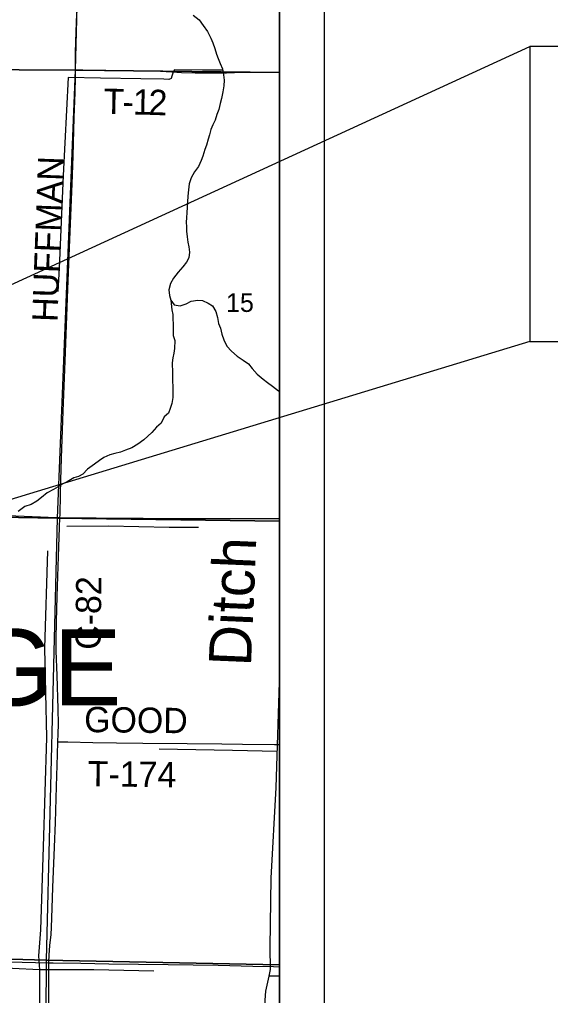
# Model space of a CAD drawing. Extents: x 0 to 39.4, y 0 to 22.
# Drawn here: x 8.317 to 9.507, y 17.227 to 19.416 of the extents above; entities that cross this region are included whole.
import ezdxf

# ---------------------------------------------------------------- set-up
doc = ezdxf.new("R2010")
doc.units = 0
for name, color, linetype in [('Default', 7, 'Continuous'), ('GM_X_County_Road', 7, 'Continuous'), ('GM_X_County_Road_Text', 7, 'Continuous'), ('GM_X_Interstate_Route', 7, 'Continuous'), ('GM_X_Minor_River', 7, 'Continuous'), ('GM_X_Minor_River_Text', 7, 'Continuous'), ('GM_X_Section', 7, 'Continuous'), ('GM_X_Section_Text', 7, 'Continuous'), ('GM_X_State_Route', 7, 'Continuous'), ('GM_X_Township_Road', 7, 'Continuous'), ('GM_X_Township_Road_Text', 7, 'Continuous'), ('GM_X_Township_Text', 7, 'Continuous'), ('SH_Data', 7, 'Continuous')]:
    doc.layers.add(name, color=color, linetype=linetype)

msp = doc.modelspace()

# ---------------------------------------------------------------- linework, layer by layer
at = {"layer": 'Default'}
for points in [[(8.9, 19.2971), (8.9, 20.3024), (8.4681, 20.3039), (8.4416, 19.3027)], [(8.9, 18.2912), (8.9, 19.2971), (8.4416, 19.3027), (8.401, 18.2978)], [(8.9, 17.2957), (8.9, 18.2912), (8.401, 18.2978), (8.3769, 17.3064)], [(8.9, 16.3001), (8.9, 17.2957), (8.3769, 17.3064), (8.3707, 16.3273)]]:
    msp.add_lwpolyline(points, close=True, dxfattribs=at)
at = {"layer": 'GM_X_County_Road'}
for points in [[(8.4422, 19.3032), (8.4421, 19.3175), (8.4427, 19.3423), (8.4442, 19.3889), (8.4455, 19.4293), (8.4473, 19.4759), (8.4489, 19.5287), (8.4524, 19.6343), (8.458, 19.7958), (8.4596, 19.8393), (8.4605, 19.8735), (8.4618, 19.917), (8.4638, 19.9822), (8.467, 20.0909), (8.4725, 20.2649), (8.4739, 20.3065)], [(8.4075, 18.2991), (8.4077, 18.305), (8.409, 18.3515), (8.4097, 18.3826), (8.4113, 18.4323), (8.4151, 18.5379), (8.4193, 18.6497), (8.4255, 18.8112), (8.4297, 18.923), (8.4318, 18.9758), (8.4347, 19.0473), (8.4371, 19.1094), (8.4398, 19.1963), (8.4417, 19.2522), (8.4422, 19.2864), (8.4422, 19.3032)], [(7.9066, 18.3132), (7.9262, 18.3132), (7.9915, 18.3125), (8.0381, 18.3111), (8.0629, 18.3103), (8.1127, 18.3094), (8.209, 18.3066), (8.2618, 18.3048), (8.3084, 18.3031), (8.3643, 18.3008), (8.3985, 18.2993), (8.4075, 18.2991)], [(8.4032, 17.7958), (8.4038, 17.8141), (8.404, 17.8359), (8.4035, 17.87), (8.4011, 17.9446), (8.3994, 18.0005), (8.3992, 18.0254), (8.3998, 18.0658), (8.401, 18.1217), (8.4044, 18.2118), (8.4066, 18.277), (8.4075, 18.2991)], [(8.4075, 18.2991), (8.4327, 18.2986), (8.4886, 18.2983), (8.5508, 18.298), (8.5943, 18.2979), (8.6596, 18.2972), (8.7311, 18.2969), (8.8026, 18.2966), (8.8772, 18.2967), (8.9, 18.2966)], [(8.3824, 17.3006), (8.3824, 17.3019), (8.3832, 17.3174), (8.3852, 17.3391), (8.3877, 17.3638), (8.3887, 17.3793), (8.3905, 17.4228), (8.3918, 17.4694), (8.3951, 17.5595), (8.3973, 17.6153), (8.4, 17.6961), (8.4022, 17.7675), (8.4032, 17.7958)], [(8.3715, 16.3333), (8.3721, 16.3573), (8.3759, 16.5157), (8.377, 16.5654), (8.3794, 16.6586), (8.381, 16.7114), (8.3832, 16.7984), (8.3843, 16.8357), (8.3844, 16.8668), (8.3837, 16.9289), (8.3834, 16.9849), (8.3834, 17.0843), (8.3832, 17.1589), (8.3826, 17.2086), (8.3825, 17.2801), (8.3824, 17.3006)]]:
    msp.add_lwpolyline(points, dxfattribs=at)
at = {"layer": 'GM_X_Interstate_Route'}
msp.add_lwpolyline([(8.9, 15.3132), (8.9, 20.9)], dxfattribs=at)
at = {"layer": 'GM_X_Minor_River'}
msp.add_line((8.9, 17.2705), (8.876, 17.2704), dxfattribs=at)
for points in [[(8.706, 19.4263), (8.7195, 19.4158), (8.7288, 19.4027), (8.7384, 19.3896), (8.7457, 19.3747), (8.7501, 19.364), (8.7552, 19.351), (8.7584, 19.3384), (8.762, 19.3288), (8.7671, 19.3177), (8.7719, 19.3059), (8.7746, 19.2921), (8.7756, 19.28), (8.775, 19.2674), (8.7728, 19.2538), (8.7695, 19.2387), (8.767, 19.2281), (8.7637, 19.2145), (8.7593, 19.2032), (8.7553, 19.1907), (8.7506, 19.1798), (8.7458, 19.1692), (8.7429, 19.1579), (8.7397, 19.1477), (8.7364, 19.1344), (8.7324, 19.1243), (8.7276, 19.1099), (8.7244, 19.0997), (8.7185, 19.0865), (8.7091, 19.0742), (8.7017, 19.061), (8.6976, 19.0474), (8.6958, 19.0338), (8.6944, 19.0197), (8.6935, 19.0072), (8.6932, 18.9947), (8.6923, 18.9833), (8.6913, 18.9712), (8.6907, 18.9617), (8.6917, 18.9511), (8.6915, 18.9416), (8.6928, 18.929), (8.6945, 18.9168), (8.6966, 18.9065), (8.6982, 18.894), (8.6965, 18.8818), (8.691, 18.8721), (8.6832, 18.8616), (8.6727, 18.8496), (8.6622, 18.8361), (8.6552, 18.8237), (8.6515, 18.8101), (8.6532, 18.7968), (8.656, 18.7865), (8.6638, 18.7761), (8.6774, 18.7743), (8.6904, 18.7783), (8.7019, 18.7841), (8.7168, 18.7865), (8.7274, 18.7856), (8.7399, 18.78), (8.7496, 18.7738), (8.7574, 18.7615), (8.761, 18.7478), (8.7634, 18.7344)], [(8.7725, 19.3028), (8.7269, 19.3029), (8.6643, 19.3033), (8.6611, 19.298), (8.6587, 19.2889), (8.6567, 19.284), (8.6517, 19.2819), (8.6403, 19.2824), (8.589, 19.283), (8.4986, 19.2843), (8.4257, 19.2864), (8.4151, 19.0663), (8.4055, 18.8584), (8.4031, 18.806)], [(8.656, 18.7865), (8.6583, 18.7652), (8.6604, 18.7545), (8.6609, 18.7435), (8.6611, 18.734), (8.6617, 18.7207), (8.6614, 18.7074), (8.665, 18.6963), (8.6643, 18.6785), (8.6626, 18.6679), (8.6605, 18.6577), (8.6595, 18.6459), (8.6599, 18.6239), (8.6601, 18.6136), (8.6599, 18.6041), (8.6605, 18.5939), (8.6607, 18.584), (8.6604, 18.5684), (8.6583, 18.5548), (8.655, 18.5434), (8.651, 18.5333), (8.641, 18.5251), (8.6347, 18.5108), (8.6239, 18.5018), (8.6134, 18.4902), (8.5956, 18.4731), (8.5825, 18.4638), (8.5691, 18.4553), (8.5549, 18.4503), (8.543, 18.4459), (8.5304, 18.4427), (8.5197, 18.4395), (8.506, 18.4337), (8.496, 18.427), (8.4848, 18.4189), (8.4694, 18.4074), (8.4589, 18.3965), (8.4489, 18.391), (8.439, 18.3878), (8.4236, 18.379), (8.4137, 18.375), (8.4033, 18.3679), (8.3929, 18.3617), (8.3791, 18.3543), (8.366, 18.3439), (8.356, 18.3361), (8.3429, 18.3287), (8.3292, 18.3237), (8.3138, 18.3129)], [(8.7634, 18.7344), (8.7674, 18.7237), (8.7705, 18.7104), (8.7752, 18.6978), (8.7818, 18.6836), (8.7919, 18.6724), (8.805, 18.6608), (8.8181, 18.6518), (8.8305, 18.644), (8.8383, 18.6336), (8.8495, 18.6205), (8.863, 18.6096), (8.8731, 18.6022), (8.8843, 18.594), (8.8974, 18.5835), (8.9, 18.5811)], [(8.4232, 18.2796), (8.5163, 18.2802), (8.6526, 18.2777), (8.7184, 18.2773)], [(8.3796, 18.2246), (8.3733, 18.0063), (8.3771, 17.8061), (8.3703, 17.5605), (8.3638, 17.3741), (8.3593, 17.316), (8.3618, 17.2848), (8.3616, 17.1762), (8.3606, 16.8731), (8.3565, 16.6533), (8.3505, 16.4353), (8.3496, 16.3256), (8.3537, 16.2978), (8.35, 16.1835), (8.3462, 16.0594), (8.343, 15.9276), (8.3395, 15.8198), (8.3375, 15.715), (8.3335, 15.5829), (8.3325, 15.4465), (8.3289, 15.3345)], [(8.9, 17.9539), (8.892, 17.6933), (8.8804, 17.4903), (8.8779, 17.3357), (8.8786, 17.2856), (8.876, 17.2704), (8.8686, 17.2371), (8.8671, 17.2166), (8.8652, 17.1794), (8.8683, 17.0958), (8.8668, 16.9093), (8.8612, 16.7229), (8.861, 16.6036), (8.8598, 16.4958), (8.8594, 16.4323), (8.8568, 16.3709), (8.856, 16.3469)], [(8.8945, 17.7746), (8.7945, 17.7764), (8.63, 17.7794)], [(8.6181, 17.2813), (8.4837, 17.2849), (8.3618, 17.2848), (8.2399, 17.2905), (8.0075, 17.297), (7.8849, 17.3008)]]:
    msp.add_lwpolyline(points, dxfattribs=at)
at = {"layer": 'GM_X_Section'}
for points in [[(8.4681, 20.3039), (8.4416, 19.3027), (7.439, 19.3083), (7.4647, 20.3092)], [(8.4416, 19.3027), (8.401, 18.2978), (7.4046, 18.3152), (7.439, 19.3083)], [(8.401, 18.2978), (8.3769, 17.3064), (7.3784, 17.3348), (7.4046, 18.3152)], [(8.3769, 17.3064), (8.3707, 16.3273), (7.3732, 16.344), (7.3784, 17.3348)]]:
    msp.add_lwpolyline(points, close=True, dxfattribs=at)
at = {"layer": 'GM_X_State_Route'}
for points in [[(6.8016, 17.3392), (6.898, 17.3386), (6.9881, 17.3378), (7.0534, 17.3371), (7.1342, 17.3365), (7.1933, 17.3358), (7.3704, 17.3333), (7.3804, 17.3331), (7.4046, 17.3325), (7.4605, 17.3304), (7.5195, 17.3285), (7.5755, 17.3267), (7.7712, 17.3196), (7.8582, 17.3167), (7.9265, 17.3146), (7.9762, 17.3125), (8.0632, 17.3097), (8.2123, 17.3053), (8.2931, 17.3024), (8.3824, 17.3006)], [(8.3824, 17.3006), (8.3926, 17.3003), (8.4547, 17.2996), (8.5169, 17.2983), (8.6505, 17.2967), (8.7065, 17.2958), (8.7624, 17.2949), (8.8401, 17.2928), (8.8867, 17.292), (8.9, 17.2917)]]:
    msp.add_lwpolyline(points, dxfattribs=at)
at = {"layer": 'GM_X_Township_Road'}
for points in [[(7.9433, 19.3081), (7.9681, 19.3078), (8.0147, 19.3076), (8.0396, 19.3072), (8.0893, 19.3067), (8.1328, 19.306), (8.1701, 19.3058), (8.2074, 19.3052), (8.2913, 19.304), (8.397, 19.3031), (8.4405, 19.3033), (8.4422, 19.3032)], [(8.4422, 19.3032), (8.4592, 19.303), (8.5618, 19.3017), (8.5991, 19.3014), (8.6332, 19.3003), (8.6581, 19.2989), (8.6798, 19.2976), (8.7109, 19.2967), (8.7357, 19.2967), (8.7575, 19.2965), (8.7754, 19.2966), (8.7812, 19.2968), (8.7864, 19.297), (8.7989, 19.2975), (8.8146, 19.298), (8.8258, 19.298), (8.841, 19.2982), (8.86, 19.2978), (8.9, 19.2972)], [(8.4032, 17.7958), (8.41, 17.7957), (8.4255, 17.7957), (8.4814, 17.7945), (8.5342, 17.7939), (8.5932, 17.7933), (8.6926, 17.7924), (8.7703, 17.7915), (8.8169, 17.7911), (8.8884, 17.7901), (8.9, 17.7899)]]:
    msp.add_lwpolyline(points, dxfattribs=at)
at = {"layer": 'SH_Data'}
for p, q in [((9, 21), (9, 14)), ((8.9, 20.9), (8.9, 14.1))]:
    msp.add_line(p, q, dxfattribs=at)
for points in [[(9.4615, 18.6937), (5.1869, 17.3921), (9.4615, 19.3557)], [(9.4615, 18.6937), (10.9611, 18.6937), (10.9611, 19.3557), (9.4615, 19.3557)]]:
    msp.add_lwpolyline(points, close=True, dxfattribs=at)

# ---------------------------------------------------------------- texts
at = {"layer": 'GM_X_County_Road_Text'}
for s, rotation, p in [('HUFFMAN', 87.8986, (8.4019, 18.7372)), ('C-82', 89.3324, (8.4988, 18.0023))]:
    msp.add_text(s, height=0.05682, rotation=rotation, dxfattribs=at).set_placement(p)
at = {"layer": 'GM_X_Minor_River_Text'}
msp.add_text('Ditch', height=0.09475, rotation=87.577, dxfattribs=at).set_placement((8.8358, 17.9644))
at = {"layer": 'GM_X_Section_Text'}
msp.add_text('15', height=0.04186, rotation=0, dxfattribs=at).set_placement((8.7801, 18.7603))
at = {"layer": 'GM_X_Township_Road_Text'}
for s, height, rotation, p in [('T', 0.0568, 358.8685, (8.5048, 19.2045)), ('1', 0.0568, 358.777, (8.5706, 19.2032)), ('2', 0.0568, 358.3344, (8.6055, 19.2024)), ('-', 0.0568, 358.8525, (8.5473, 19.2037)), ('GOOD', 0.05682, 359.2898, (8.4616, 17.8179)), ('T-174', 0.05682, 359.4379, (8.4697, 17.6961))]:
    msp.add_text(s, height=height, rotation=rotation, dxfattribs=at).set_placement(p)
at = {"layer": 'GM_X_Township_Text'}
msp.add_text('PORTAGE', height=0.17045, rotation=0, dxfattribs=at).set_placement((7.4309, 17.8777))

doc.saveas('drawing.dxf')
